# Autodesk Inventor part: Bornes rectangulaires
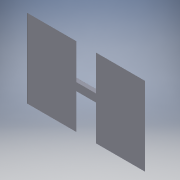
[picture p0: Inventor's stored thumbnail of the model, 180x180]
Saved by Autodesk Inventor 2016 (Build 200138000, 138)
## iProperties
Created: 2018-03
Part Number: Bornes rectangulaires
Material: Générique
Document SubType Name: Modeling
Designer: Bruno
Density: 1 g/cm^3
Appearance: Par défaut
Author: Bruno
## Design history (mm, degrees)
feature "Composite1"
body "Srf1"
